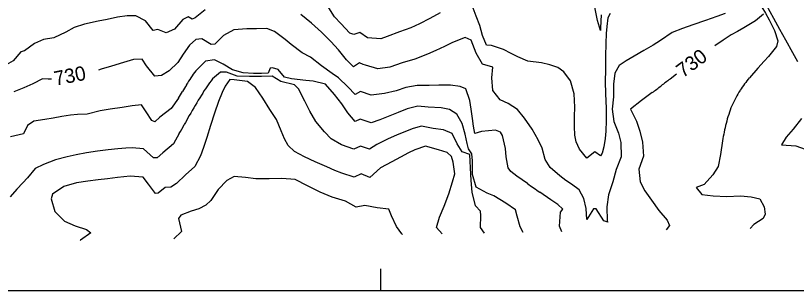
# Model space of a CAD drawing. Extents: x 2566079 to 2571326, y 424054 to 426896.
# Drawn here: x 2569490 to 2570581, y 424077 to 424461 of the extents above; entities that cross this region are included whole.
import ezdxf

# ---------------------------------------------------------------- set-up
doc = ezdxf.new("R2010")
doc.units = 0
for name, color, linetype in [('Contour_ADS_Label_Major', 7, 'Continuous'), ('Contour_ADS_Major', 7, 'Continuous'), ('Contour_ADS_Minor', 7, 'Continuous'), ('Contour_ADS_State_Plane_Border', 7, 'Continuous')]:
    doc.layers.add(name, color=color, linetype=linetype)

msp = doc.modelspace()

# ---------------------------------------------------------------- linework, layer by layer
at = {"layer": 'Contour_ADS_Major'}
msp.add_line((2570413.6, 424379.6), (2570404.5, 424372.7), dxfattribs=at)
for points in [[(2570535.3, 424463.3), (2570523.8, 424453.9), (2570507.8, 424444.4), (2570498.9, 424439.3), (2570490.1, 424434.4), (2570478.5, 424427.2), (2570467.2, 424419.3)], [(2570205.1, 424226.5), (2570190.4, 424237), (2570181.8, 424243.6), (2570178, 424248.4), (2570175.6, 424264.1), (2570174.4, 424275.4), (2570170.5, 424293.7), (2570167.7, 424298.5), (2570160.5, 424301.4), (2570141, 424299.2), (2570131.8, 424296.6), (2570129.8, 424306.9), (2570128.4, 424317.7), (2570126.6, 424330.5), (2570124.8, 424342.8), (2570119.2, 424358.8), (2570111, 424362.5), (2570097.4, 424364), (2570081.4, 424364), (2570067.6, 424363.5), (2570051.1, 424363.5), (2570035.1, 424361), (2570021.5, 424356.4), (2570005.5, 424352.3), (2569986.7, 424350.2), (2569972, 424355.1), (2569964.2, 424351), (2569954.3, 424361.8), (2569941.2, 424374.3), (2569932.4, 424380.4), (2569917.2, 424391), (2569901.8, 424403.1), (2569890.1, 424409.4), (2569875.1, 424420.8), (2569866.7, 424427.9), (2569851.4, 424439.1), (2569840.7, 424443.6), (2569826.2, 424442.9), (2569812.8, 424443), (2569794.7, 424441.5), (2569780.4, 424433.4), (2569768, 424421.3), (2569763.1, 424421.1), (2569749.9, 424428.8), (2569741.6, 424428.2), (2569732.7, 424420), (2569723.9, 424407.4), (2569716.6, 424395.8), (2569704.4, 424384.2), (2569693.6, 424377.6), (2569684.4, 424376.6), (2569672.5, 424391), (2569666.6, 424400.7), (2569654.5, 424400), (2569640.5, 424395.9), (2569623.9, 424390.9), (2569609.4, 424386.5), (2569605.5, 424385.3)], [(2569540.1, 424372.5), (2569535.1, 424372.7), (2569527.1, 424373), (2569513.7, 424366.2), (2569501.4, 424360.6), (2569487, 424354.9)], [(2570379.6, 424353.8), (2570364.7, 424342.7), (2570349.1, 424330.8), (2570357.4, 424313.6), (2570362.1, 424299.7), (2570366, 424284.2), (2570367.4, 424264.8), (2570360.9, 424246.8), (2570362.7, 424228.9), (2570369.2, 424216.3), (2570378.4, 424203.5), (2570388.8, 424189), (2570400.4, 424175.4), (2570403.6, 424167.9), (2570399.2, 424161.8)], [(2570253.3, 424159.2), (2570250.1, 424166.8), (2570251.3, 424186.5), (2570254.5, 424190.7), (2570247.7, 424197.2), (2570237.8, 424203.8), (2570222.5, 424214.4)]]:
    msp.add_lwpolyline(points, dxfattribs=at)
for centre, radius, start, end in [((2580840.7, 410584.8), 17292.2, 127.12256, 127.17435), ((2568520.2, 426819), 3087.8, 307.0256, 307.3156), ((2571891.5, 426627.6), 2934.1, 234.9167, 235.3299)]:
    msp.add_arc(centre, radius, start, end, dxfattribs=at)
at = {"layer": 'Contour_ADS_Minor'}
for points in [[(2570469.4, 424580.2), (2570478.3, 424564.4), (2570485.1, 424552.3), (2570494.8, 424534.9), (2570504.2, 424518.9), (2570510.5, 424508.9), (2570517, 424498.7), (2570526.3, 424483.9), (2570532.8, 424473.2), (2570537.7, 424465), (2570543.2, 424455.6), (2570550.5, 424440.8), (2570554.9, 424426.1), (2570553.2, 424418.4), (2570541.9, 424404.2), (2570535.8, 424397.5), (2570527.1, 424387.9), (2570515.3, 424374.4)], [(2570582.9, 424477), (2570572.9, 424483.9), (2570558.3, 424493.3), (2570543.9, 424504.2), (2570531.9, 424512.5), (2570527, 424514.9), (2570525.6, 424510.5), (2570531.4, 424493.1), (2570538.9, 424476.5), (2570544, 424467), (2570549.1, 424457.7), (2570557.5, 424442.4), (2570565.8, 424427.4), (2570575.7, 424410), (2570582.7, 424397.4)], [(2570083.1, 424465.4), (2570068.5, 424457.3), (2570054.1, 424449.9), (2570042.1, 424444.4), (2570026.1, 424438.6), (2570009.1, 424432), (2570000.1, 424428.8), (2569981.4, 424430.5), (2569971, 424437.6), (2569962.5, 424434.8), (2569956.9, 424436.7), (2569944.2, 424450.4), (2569935.6, 424459.8), (2569925.4, 424475.8)], [(2570320.9, 424464.5), (2570317.3, 424458.2), (2570315.9, 424446.1), (2570315.3, 424436.3), (2570314.7, 424422.6), (2570314.3, 424404.7), (2570314.1, 424385.6), (2570314, 424369.3), (2570314.3, 424351.8), (2570315.1, 424331.9), (2570315, 424314.8), (2570314.9, 424300), (2570313.7, 424289.4), (2570311.8, 424278), (2570309.7, 424269.1), (2570307.4, 424265.2), (2570299.2, 424270.8), (2570288.3, 424262.1), (2570278.1, 424274.7), (2570273.3, 424284.9), (2570271.4, 424294.1), (2570270.8, 424306.5), (2570271, 424320.5), (2570271.3, 424333.6), (2570270.4, 424351.9), (2570265.3, 424370.4), (2570255.9, 424382.9), (2570247.6, 424388.7), (2570236.5, 424392.7), (2570224.8, 424395.2), (2570205.8, 424397.8), (2570191.6, 424403.7), (2570182.2, 424408.5), (2570171.5, 424413.8), (2570154.9, 424419.8), (2570147.9, 424420.1), (2570142.4, 424433.4), (2570138.5, 424447.8), (2570133.3, 424460.8), (2570126.5, 424479.3)], [(2570308, 424462.7), (2570307.4, 424444.3), (2570307.1, 424440.8), (2570303.2, 424454.7), (2570299.4, 424473.1)], [(2569754.5, 424469.4), (2569740.8, 424458.3), (2569736.4, 424456.4), (2569730.8, 424459.6), (2569723.6, 424455.9), (2569711.8, 424442.4), (2569700.1, 424437.4), (2569688.6, 424442.2), (2569682, 424440.8), (2569671.4, 424454), (2569657.6, 424461.3), (2569645.8, 424461.3), (2569632, 424459.2), (2569617.8, 424456.2)], [(2570481.3, 424464.6), (2570469.8, 424460.2), (2570453.8, 424454.5), (2570436.4, 424448.5), (2570421.7, 424443.4), (2570407.3, 424437.7), (2570391, 424426.5), (2570380.9, 424420.1), (2570367.9, 424412.4), (2570354.3, 424404.7), (2570343.2, 424398.3), (2570333.5, 424391.8), (2570327.4, 424381), (2570325.4, 424365.6), (2570325.6, 424347.6), (2570323.5, 424330.4), (2570325.9, 424313.5), (2570332.6, 424297.2), (2570335.5, 424283.9), (2570336, 424264.1), (2570329.3, 424246.4), (2570324.3, 424229.1), (2570318.2, 424210.7), (2570316.2, 424193.8), (2570316.8, 424174.6), (2570317.3, 424172.5), (2570311.8, 424174.2), (2570301.4, 424191.1), (2570297.3, 424191.3), (2570288.3, 424176.1), (2570287, 424191.7), (2570283.8, 424205.6), (2570277.6, 424217.6), (2570266.9, 424225.6), (2570259, 424231), (2570250.5, 424237.2), (2570236.8, 424249), (2570229.9, 424260.3), (2570225.5, 424276), (2570220.3, 424287.8), (2570211.6, 424302.8), (2570201, 424318.1), (2570191.1, 424330.2), (2570178.3, 424338.7), (2570166.9, 424343.8), (2570156.8, 424356.8), (2570155.5, 424374.4), (2570156.8, 424389.1), (2570142.1, 424393.4), (2570133.4, 424409.1), (2570126.6, 424427.2), (2570118.3, 424430.6), (2570100.6, 424423.9), (2570089.2, 424418.3), (2570077, 424412.5), (2570065.3, 424407.3), (2570047.7, 424400.5), (2570030.1, 424395.4), (2570012.9, 424389.4), (2569996.2, 424387.2), (2569978.6, 424392), (2569975.6, 424393.2), (2569970.3, 424395.3), (2569962, 424389.8), (2569952.4, 424399.4), (2569941, 424413.6), (2569930.5, 424425.1), (2569917.3, 424438.4), (2569903.2, 424450.7), (2569888.6, 424462.9)], [(2569617.8, 424456.2), (2569605, 424453.5), (2569586.2, 424449.5), (2569571.5, 424444.9), (2569559.8, 424438.1), (2569543, 424430.4), (2569528.5, 424428), (2569516.1, 424422.4), (2569502, 424412), (2569496.8, 424410.6), (2569486.4, 424398), (2569473.2, 424390.5), (2569457.5, 424382.9)], [(2570199.3, 424158.2), (2570194.9, 424166), (2570190.8, 424181), (2570188.6, 424190), (2570175.1, 424198.9), (2570158.1, 424209.3), (2570148.7, 424213.3), (2570133.6, 424221.4), (2570128.5, 424239.4), (2570128.3, 424258.4), (2570127.4, 424268.1), (2570122.7, 424275.1), (2570121, 424282.4), (2570118.3, 424295.5), (2570113.8, 424310.7), (2570106.6, 424323.5), (2570096.2, 424330.3), (2570084.7, 424332.5), (2570066.3, 424333.4), (2570051.8, 424335), (2570037, 424331), (2570024.5, 424326.1), (2570010.6, 424320.5), (2569998.7, 424315.6), (2569986.7, 424311.6), (2569971.5, 424316.5), (2569964.3, 424313.2), (2569954, 424325.3), (2569945.9, 424337.9), (2569935.4, 424351.1), (2569922.9, 424365.6), (2569905.5, 424369.7), (2569895.2, 424370.8), (2569875.4, 424372.8), (2569865.4, 424375.1), (2569856.7, 424386.1), (2569848.7, 424388.6), (2569845.3, 424388), (2569842.6, 424381), (2569833.5, 424380.6), (2569822.2, 424380.3), (2569807.8, 424381.4), (2569793.1, 424385.6), (2569780, 424393.4), (2569767.9, 424399.6), (2569755.3, 424397.9), (2569741.6, 424384.3)], [(2570144.9, 424157.2), (2570139.4, 424165.2), (2570139.9, 424181.9), (2570139.3, 424187.8), (2570132.4, 424195.2), (2570128, 424214.4), (2570126.3, 424231), (2570125.6, 424248.7), (2570124.4, 424267.2), (2570113.8, 424271.1), (2570106.9, 424281.9), (2570100, 424296.6), (2570087.8, 424301.5), (2570073.5, 424303.5), (2570057.2, 424306.9), (2570045.3, 424303.7), (2570034.7, 424299.4), (2570022.3, 424294.2), (2570010.5, 424288.9), (2569994.5, 424281), (2569984.3, 424274.5), (2569971.6, 424278.6), (2569962.7, 424274.6), (2569945.1, 424280.6), (2569930.8, 424289.1), (2569921.4, 424298.8), (2569909.2, 424313.4), (2569900.9, 424327.7), (2569894, 424341.6), (2569885.3, 424358.8), (2569879.4, 424364.8), (2569860.2, 424369.4), (2569848.3, 424376.5), (2569833.2, 424376.2), (2569816.7, 424376.1), (2569799.2, 424376.6), (2569784.3, 424382.4), (2569776.2, 424382.4), (2569764.9, 424372.8)], [(2570086, 424156.1), (2570078.1, 424165.3), (2570082.4, 424179.7), (2570088.9, 424195), (2570095.3, 424212.1), (2570100.2, 424229.1), (2570103.7, 424240.1), (2570101.2, 424256.6), (2570098.8, 424264.3), (2570092.8, 424270.1), (2570080.7, 424273.6), (2570062.7, 424278.8), (2570047.8, 424273.8), (2570039.1, 424269.5), (2570027.6, 424263.5), (2570015.4, 424257), (2569999.7, 424248.5), (2569984.9, 424235.2), (2569972.8, 424240), (2569962.8, 424235.7), (2569945.8, 424241.1), (2569936.1, 424245), (2569924.7, 424249.7), (2569908.4, 424256.7), (2569893.6, 424264), (2569879.6, 424271.2), (2569870.7, 424279.7), (2569865.6, 424289.3), (2569860.7, 424300.4), (2569854.5, 424316.3), (2569844.9, 424329.9), (2569835.3, 424345.9), (2569825, 424361.1), (2569814, 424369.2), (2569795.3, 424371.7), (2569789, 424372.2), (2569782.6, 424362.9), (2569778.2, 424353.8), (2569773.1, 424341.1), (2569767.6, 424325.2), (2569762.2, 424307.8), (2569757, 424291), (2569752.4, 424276.8), (2569748.2, 424265.4), (2569740.1, 424250.5), (2569727.4, 424238.8), (2569714.4, 424226.4), (2569706.8, 424221.5), (2569698.7, 424221), (2569689, 424213.2), (2569685.4, 424212.6), (2569675.5, 424225.6), (2569667.8, 424235.3), (2569650, 424236.7), (2569632.2, 424235), (2569618.3, 424233.1), (2569605.2, 424231.7), (2569590.5, 424229.9), (2569574.8, 424227.4), (2569557.1, 424222.2), (2569541.1, 424211.7), (2569539.5, 424205.1), (2569544.4, 424187.6), (2569558.2, 424174.1), (2569572.9, 424167.6), (2569588.6, 424162.2), (2569594.9, 424157.6), (2569580.2, 424147.2), (2569579.8, 424146.9)], [(2569717.5, 424346.1), (2569707.2, 424331.3), (2569691.4, 424319.4), (2569684.3, 424312.9), (2569680.3, 424314.6), (2569672, 424326.9), (2569665.6, 424336.5), (2569652.8, 424335.1), (2569638.6, 424333), (2569622, 424330.5), (2569607.8, 424328.1), (2569589.5, 424323.5), (2569576.4, 424323.2), (2569566.4, 424322.2), (2569554.5, 424320.3), (2569542, 424318), (2569530.7, 424316.1), (2569515.1, 424314), (2569506.5, 424307.7), (2569500.8, 424296.3), (2569482.7, 424291.8)], [(2570588.1, 424317.3), (2570576.4, 424302.6), (2570566.9, 424291.3), (2570560.4, 424280.8), (2570580.1, 424279.3), (2570593.1, 424274.5)], [(2569718.5, 424296.4), (2569710.5, 424282.2), (2569695.3, 424269.5), (2569687.8, 424262.6), (2569682.4, 424262.5), (2569668.4, 424275.1), (2569652.8, 424276.4), (2569643.9, 424275.8), (2569632.4, 424274.9), (2569618.9, 424273.8), (2569604.1, 424272), (2569588.8, 424269.4), (2569574.3, 424266.5), (2569561.9, 424263.7), (2569545.3, 424259.8), (2569528.7, 424253.4), (2569517, 424247.8), (2569506.3, 424234.7), (2569499.6, 424227.6), (2569491.3, 424218.6), (2569482.1, 424208.1)], [(2570477.9, 424286.5), (2570475, 424267.3), (2570471.5, 424250.5), (2570464.1, 424238.9), (2570452.3, 424225.2), (2570441.1, 424220.8), (2570448.8, 424211.4), (2570464.6, 424209.3), (2570483.8, 424208.6), (2570503.1, 424209.2), (2570518, 424207.9), (2570529.8, 424205), (2570536, 424194), (2570537.5, 424183.6), (2570534.6, 424177.8), (2570521.4, 424169.1), (2570516.4, 424163.9)], [(2570030.4, 424155.1), (2570029.4, 424156.2), (2570022.1, 424166.6), (2570015.3, 424181.4), (2570011.3, 424190.9), (2569995.1, 424192.6), (2569977.8, 424195.9), (2569965.7, 424193.5), (2569950.8, 424202.1), (2569932.1, 424207.7), (2569915.3, 424214.5), (2569897.9, 424223.4), (2569880.3, 424232.3), (2569861.7, 424233.6), (2569843.9, 424233), (2569825.3, 424233.2), (2569811.2, 424235.1), (2569795, 424236.4), (2569784.9, 424230.8), (2569772.9, 424218.4), (2569762.6, 424202.9), (2569755.5, 424196.2), (2569745.7, 424191.3), (2569735.1, 424187.7), (2569720.7, 424182.4), (2569717.2, 424177.7), (2569721.6, 424159.5), (2569710.7, 424149.3)]]:
    msp.add_lwpolyline(points, dxfattribs=at)
for centre, radius, start, end in [((2569944.3, 424234.4), 252.1, 143.5061, 148.9546), ((2570667.9, 424248), 198.2, 140.3647, 146.6638), ((2570066.9, 424158.7), 396.1, 148.7242, 150.257), ((2569964.7, 424218.7), 252.3, 142.3406, 148.593), ((2569496.6, 424482.5), 259.6, 328.3212, 330.66), ((2570628.7, 424275.6), 150.2, 147.2352, 156.5452), ((2570516.5, 423880.2), 899.7, 148.5077, 150.6276), ((2570661.9, 424266.2), 184.5, 157.9928, 166.0712), ((2570930.1, 423645.7), 1375.2, 150.5649, 151.1631), ((2567406.6, 425593.3), 2650.8, 330.7088, 331.0192), ((2570793.3, 424234.5), 319.7, 166.2181, 170.6431)]:
    msp.add_arc(centre, radius, start, end, dxfattribs=at)
at = {"layer": 'Contour_ADS_State_Plane_Border'}
msp.add_line((2570000, 424077.1), (2570000, 424107.1), dxfattribs=at)
msp.add_lwpolyline([(2566079.3, 424077.1), (2571302.9, 424077.1), (2571302.9, 426873.7), (2566079.3, 426873.7), (2566079.3, 424077.1)], close=True, dxfattribs=at)

# ---------------------------------------------------------------- texts
at = {"layer": 'Contour_ADS_Label_Major'}
for rotation, p in [(36.5496, (2570422.5, 424373.7)), (11.1079, (2569545.5, 424363.3))]:
    msp.add_text('730', height=20, rotation=rotation, dxfattribs=at).set_placement(p)

doc.saveas('drawing.dxf')
